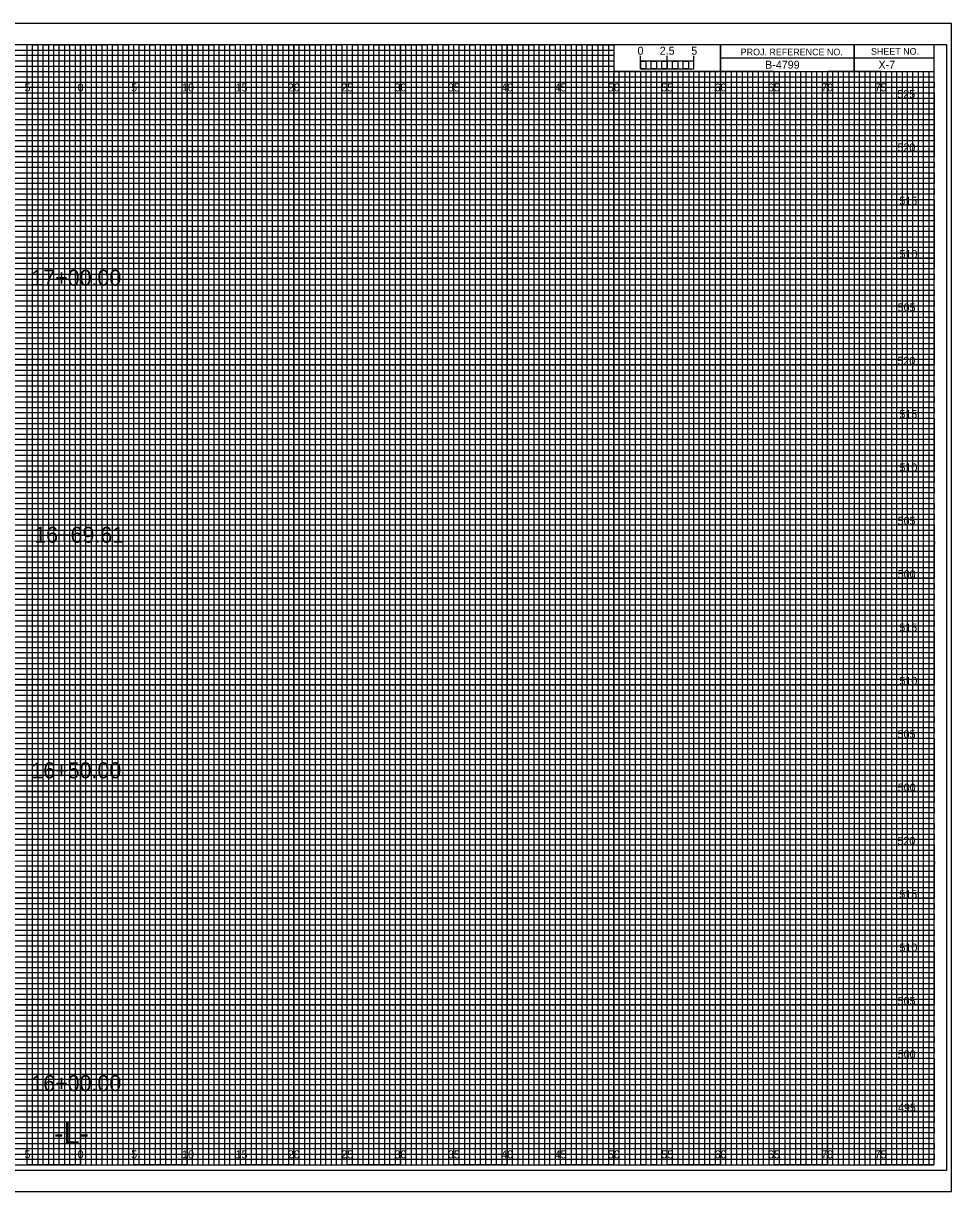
# Model space of a CAD drawing. Extents: x -7 to 162, y 768 to 877.
# Drawn here: x 74.6 to 161.7, y 767.5 to 877 of the extents above; entities that cross this region are included whole.
import ezdxf

# ---------------------------------------------------------------- set-up
doc = ezdxf.new("R2010")
doc.units = 0
for name, color, linetype in [('Prop XS Alignment Label', 7, 'Continuous'), ('Prop XS Bar Scale Labels', 7, 'Continuous'), ('Prop XS Elevation Labels', 7, 'Continuous'), ('Prop XS Offset Labels', 7, 'Continuous'), ('Prop XS Project Number', 7, 'Continuous'), ('Prop XS Sheet Number', 7, 'Continuous'), ('Prop XS Station Labels', 7, 'Continuous'), ('Sheet Cross Section CELL', 7, 'Continuous'), ('Sheet Cross Section Grid Major CELL', 7, 'Continuous'), ('Sheet Cross Section Grid Middle CELL', 7, 'Continuous'), ('Sheet Cross Section Grid Minor 1 CELL', 7, 'Continuous'), ('Sheet Cross Section Grid Minor 2 CELL', 7, 'Continuous'), ('Sheet Cross Section Scale CELL', 7, 'Continuous'), ('Sheet Cutting Line CELL', 7, 'Continuous'), ('Sheet DOT Grid CELL', 7, 'Continuous'), ('Sheet Plot Border Inside CELL', 7, 'Continuous'), ('Sheet Plot Border Outside CELL', 7, 'Continuous')]:
    doc.layers.add(name, color=color, linetype=linetype)

msp = doc.modelspace()

# ---------------------------------------------------------------- linework, layer by layer
at = {"layer": 'Sheet Cross Section CELL'}
for p, q in [((152.5, 875), (152.5, 872.5)), ((152.5, 872.5), (152.5, 875)), ((160, 873.75), (140, 873.75)), ((140, 873.75), (140, 872.5)), ((140, 872.5), (160, 872.5))]:
    msp.add_line(p, q, dxfattribs=at)
for points in [[(160, 875), (0, 875), (0, 770), (160, 770)], [(140, 875), (130, 875), (130, 872.51), (140, 872.51)], [(160, 875), (140, 875), (140, 872.5), (160, 872.5)]]:
    msp.add_lwpolyline(points, close=True, dxfattribs=at)
at = {"layer": 'Sheet Cross Section Grid Major CELL'}
for p, q in [((75, 875), (70, 875)), ((75, 770), (75, 875)), ((85, 875), (80, 875)), ((80, 875), (80, 770)), ((85, 770), (85, 875)), ((95, 875), (90, 875)), ((90, 875), (90, 770)), ((95, 770), (95, 875)), ((105, 875), (100, 875)), ((100, 875), (100, 770)), ((105, 770), (105, 875)), ((115, 875), (110, 875)), ((110, 875), (110, 770)), ((115, 770), (115, 875)), ((125, 875), (120, 875)), ((120, 875), (120, 770)), ((125, 770), (125, 875)), ((130, 875), (130, 770)), ((135, 770), (135, 872.5)), ((145, 872.5), (140, 872.5)), ((140, 872.5), (140, 770)), ((145, 770), (145, 872.5)), ((155, 872.5), (150, 872.5)), ((150, 872.5), (150, 770)), ((155, 770), (155, 872.5)), ((80, 770), (75, 770)), ((90, 770), (85, 770)), ((100, 770), (95, 770)), ((110, 770), (105, 770)), ((120, 770), (115, 770)), ((130, 770), (125, 770)), ((140, 770), (135, 770)), ((150, 770), (145, 770)), ((160, 770), (155, 770)), ((160, 770), (160, 770))]:
    msp.add_line(p, q, dxfattribs=at)
for points in [[(0, 870), (160, 870), (160, 865), (0, 865)], [(0, 860), (160, 860), (160, 855), (0, 855)], [(0, 850), (160, 850), (160, 845), (0, 845)], [(0, 840), (160, 840), (160, 835), (0, 835)], [(0, 830), (160, 830), (160, 825), (0, 825)], [(0, 820), (160, 820), (160, 815), (0, 815)], [(0, 810), (160, 810), (160, 805), (0, 805)], [(0, 800), (160, 800), (160, 795), (0, 795)], [(0, 790), (160, 790), (160, 785), (0, 785)], [(0, 780), (160, 780), (160, 775), (0, 775)]]:
    msp.add_lwpolyline(points, dxfattribs=at)
at = {"layer": 'Sheet Cross Section Grid Middle CELL'}
for points in [[(72.5, 770), (77.5, 770), (77.5, 875), (82.5, 875), (82.5, 770), (87.5, 770), (87.5, 875), (92.5, 875), (92.5, 770), (97.5, 770), (97.5, 875), (102.5, 875), (102.5, 770), (107.5, 770), (107.5, 875), (112.5, 875), (112.5, 770), (117.5, 770), (117.5, 875), (122.5, 875), (122.5, 770), (127.5, 770), (127.5, 875), (129.97, 875), (130, 875), (130, 872.5), (132.5, 872.5), (132.5, 770), (137.5, 770), (137.5, 872.5), (142.5, 872.5), (142.5, 770), (147.5, 770), (147.5, 872.5), (152.5, 872.5), (152.5, 770), (157.5, 770), (157.5, 872.5)], [(0, 872.5), (137.5, 872.5)], [(0, 862.5), (160, 862.5), (160, 867.5), (0, 867.5)], [(0, 852.5), (160, 852.5), (160, 857.5), (0, 857.5)], [(0, 842.5), (160, 842.5), (160, 847.5), (0, 847.5)], [(0, 832.5), (160, 832.5), (160, 837.5), (0, 837.5)], [(0, 822.5), (160, 822.5), (160, 827.5), (0, 827.5)], [(0, 812.5), (160, 812.5), (160, 817.5), (0, 817.5)], [(0, 802.5), (160, 802.5), (160, 807.5), (0, 807.5)], [(0, 792.5), (160, 792.5), (160, 797.5), (0, 797.5)], [(0, 782.5), (160, 782.5), (160, 787.5), (0, 787.5)], [(0, 772.5), (160, 772.5), (160, 777.5), (0, 777.5)]]:
    msp.add_lwpolyline(points, dxfattribs=at)
at = {"layer": 'Sheet Cross Section Grid Minor 1 CELL'}
for p, q in [((0, 874.5), (130, 874.5)), ((130, 873.99), (0, 873.99)), ((130, 874.5), (130, 873.99)), ((0, 873.5), (130, 873.5)), ((130, 872.95), (0, 872.95)), ((130, 873.5), (130, 872.95)), ((0, 872), (160, 872))]:
    msp.add_line(p, q, dxfattribs=at)
for points in [[(0, 871.5), (135, 871.5), (160, 871.5), (160, 871), (0, 871)], [(0, 870.5), (160, 870.5), (160, 869.5), (0, 869.5)], [(0, 869), (160, 869), (160, 868.5), (0, 868.49)], [(0, 868), (160, 868), (160, 867), (0, 867)], [(0, 866.5), (160, 866.5), (160, 866), (0, 866)], [(0, 865.5), (160, 865.5), (160, 864.5), (0, 864.5)], [(0, 864), (160, 864), (160, 863.5), (0, 863.5)], [(0, 863), (160, 863), (160, 862), (0, 862)], [(0, 861.5), (160, 861.5), (160, 861), (0, 861)], [(0, 860.5), (160, 860.5), (160, 859.5), (0, 859.5)], [(0, 859), (160, 859), (160, 858.5), (0, 858.5)], [(0, 858), (160, 858), (160, 856.98), (160, 856.5), (160, 856), (0, 856)], [(0, 857), (160, 857), (160, 856.5), (0, 856.5)], [(0, 855.5), (160, 855.5), (160, 854.5), (0, 854.51)], [(0, 854.51), (160, 854.5), (160, 854), (0, 854)], [(0, 853.5), (160, 853.5), (160, 853), (0, 853)], [(0, 852), (160, 852), (160, 851.5), (0, 851.5)], [(0, 851), (160, 851), (160, 850.5), (0, 850.5)], [(-0.04, 849.45), (160, 849.45), (160, 848.94), (-0.04, 848.94)], [(0, 848.5), (160, 848.5), (160, 848), (0, 848)], [(0, 847), (160, 847), (160, 846.5), (0, 846.5)], [(0, 846), (160, 846), (160, 845.5), (0, 845.5)], [(0, 844.5), (160, 844.5), (160, 844), (0, 844)], [(0, 843.5), (160, 843.5), (160, 843), (0, 843)], [(0, 842), (160, 842), (160, 841.5), (0, 841.5)], [(0, 841), (160, 841), (160, 840.5), (0, 840.5)], [(0, 839.5), (160, 839.5), (160, 838.99), (0, 839)], [(0, 838.5), (160, 838.5), (160, 838), (0, 838)], [(0, 837), (160, 837), (160, 836.5), (0, 836.5)], [(0, 836), (160, 836), (160, 835.5), (0, 835.5)], [(0, 834.5), (160, 834.5), (160, 834), (0, 834)], [(0, 833.5), (160, 833.5), (160, 833), (0, 833)], [(0, 832), (160, 832), (160, 831.5), (0, 831.5)], [(0, 831), (160, 831), (160, 830.5), (0, 830.5)], [(0, 829.5), (160, 829.5), (160, 829), (0, 829)], [(0, 828.5), (160.03, 828.46), (160, 828), (0, 828)], [(0, 827), (160, 827), (160, 826.5), (0, 826.5)], [(0, 826), (160, 826), (160, 825.5), (0, 825.5)], [(0, 824.5), (160, 824.5), (160, 824), (0, 824)], [(0, 823.5), (160, 823.5), (160, 823), (0, 823)], [(0, 822), (160, 822), (160, 821.5), (0, 821.5)], [(0, 821), (160, 821), (160, 820.5), (0, 820.5)], [(0, 819.5), (160, 819.5), (160, 819), (0, 819)], [(0, 818.5), (160, 818.5), (160, 818), (0, 818)], [(0, 817), (160, 817), (160, 816.5), (0, 816.5)], [(0, 816), (160, 816), (160, 815.5), (0, 815.5)], [(0, 814.5), (160, 814.5), (160, 814), (0, 814)], [(0, 813.5), (160, 813.5), (160, 813), (0, 813)], [(0, 812), (160, 812), (160, 811.5), (0, 811.5)], [(0, 811), (160, 811), (160, 810.5), (0, 810.5)], [(0, 809.5), (160, 809.5), (160, 808.99), (0, 809)], [(0, 808.5), (160, 808.5), (160, 808), (0, 808)], [(0, 807), (160, 807), (160, 806.5), (0, 806.5)], [(0, 806), (160, 806), (160, 805.5), (0, 805.5)], [(0, 804.5), (160, 804.5), (160, 804), (0, 804)], [(0, 803.5), (160, 803.5), (160, 803), (0, 803)], [(0, 802), (160, 802), (160, 801.5), (0, 801.5)], [(0, 801), (160, 801), (160, 800.5), (0, 800.5)], [(0, 799.5), (160, 799.5), (160, 799), (0, 799)], [(0, 798.5), (160.03, 798.46), (160, 798), (0, 798)], [(0, 797), (160, 797), (160, 796.5), (0, 796.5)], [(0, 796), (160, 796), (160, 795.5), (0, 795.5)], [(0, 794.5), (160, 794.5), (160, 794), (0, 794)], [(0, 793.5), (160, 793.5), (160, 793), (0, 793)], [(0, 792), (160, 792), (160, 791.5), (0, 791.5)], [(0, 791), (160, 791), (160, 790.5), (0, 790.5)], [(0, 789.5), (160, 789.5), (160, 789), (0, 789)], [(0, 788.5), (160, 788.5), (160, 788), (0, 788)], [(0, 787), (160, 787), (160, 786.5), (0, 786.5)], [(0, 786), (160, 786), (160, 785.5), (0, 785.5)], [(0, 784.5), (160, 784.5), (160, 784), (0, 784)], [(0, 783.5), (160, 783.5), (160, 783), (0, 783)], [(0, 782), (160, 782), (160, 781.5), (0, 781.5)], [(0, 781), (160, 781), (160, 780.5), (0, 780.5)], [(0, 779.5), (160, 779.5), (160, 779), (0, 779)], [(0, 778.5), (160, 778.5), (160, 778), (0, 778)], [(0, 777), (160, 777), (160, 776.5), (0, 776.5)], [(0, 776), (160, 776), (160, 775.5), (0, 775.5)], [(0, 774.5), (160, 774.5), (160, 774), (0, 774)], [(0, 773.5), (160, 773.5), (160, 773), (0, 773)], [(0, 772), (160, 772), (160, 771.5), (0, 771.5)], [(0, 771), (160, 771), (160, 770.5), (0, 770.5)]]:
    msp.add_lwpolyline(points, dxfattribs=at)
at = {"layer": 'Sheet Cross Section Grid Minor 2 CELL'}
for p, q in [((133.5, 872.5), (133, 872.5)), ((133, 872.5), (133, 770)), ((133.5, 770), (133.5, 872.5)), ((134.5, 872.5), (134, 872.5)), ((134, 872.5), (134, 770)), ((134.5, 770), (134.5, 872.5)), ((133, 770), (132.5, 770)), ((134, 770), (133.5, 770))]:
    msp.add_line(p, q, dxfattribs=at)
for points in [[(75, 770), (75.5, 770), (75.5, 875), (76, 875), (76, 770)], [(76, 770), (76.5, 770), (76.5, 875), (77, 875), (77, 770)], [(77.5, 770), (78, 770), (78, 875), (78.5, 875), (78.5, 770)], [(78.5, 770), (79, 770), (79, 875), (79.5, 875), (79.5, 770)], [(80, 770), (80.5, 770), (80.5, 875), (81, 875), (81, 770)], [(81, 770), (81.5, 770), (81.5, 875), (82, 875), (82, 770)], [(82.5, 770), (83, 770), (83, 875), (83.5, 875), (83.5, 770)], [(83.5, 770), (84, 770), (84, 875), (84.5, 875), (84.5, 770)], [(85, 770), (85.5, 770), (85.5, 875), (86, 875), (86, 770)], [(86, 770), (86.5, 770), (86.5, 875), (87, 875), (87, 770)], [(87.5, 770), (88, 770), (88, 875), (88.5, 875), (88.5, 770)], [(88.5, 770), (89, 770), (89, 875), (89.5, 875), (89.5, 770)], [(90, 770), (90.5, 770), (90.5, 875), (91, 875), (91, 770)], [(91, 770), (91.5, 770), (91.5, 875), (92, 875), (92, 770)], [(92.5, 770), (93, 770), (93, 875), (93.5, 875), (93.5, 770)], [(93.5, 770), (94, 770), (94, 875), (94.5, 875), (94.5, 770)], [(95, 770), (95.5, 770), (95.5, 875), (96, 875), (96, 770)], [(96, 770), (96.5, 770), (96.5, 875), (97, 875), (97, 770)], [(97.5, 770), (98, 770), (98, 875), (98.5, 875), (98.5, 770)], [(98.5, 770), (99, 770), (99, 875), (99.5, 875), (99.5, 770)], [(100, 770), (100.5, 770), (100.5, 875), (101, 875), (101, 770)], [(101, 770), (101.5, 770), (101.5, 875), (102, 875), (102, 770)], [(102.5, 770), (103, 770), (103, 875), (103.5, 875), (103.5, 770)], [(103.5, 770), (104, 770), (104, 875), (104.5, 875), (104.5, 770)], [(105, 770), (105.5, 770), (105.5, 875), (106, 875), (106, 770)], [(106, 770), (106.5, 770), (106.5, 875), (107, 875), (107, 770)], [(107.5, 770), (108, 770), (108, 875), (108.5, 875), (108.5, 770)], [(108.5, 770), (109, 770), (109, 875), (109.5, 875), (109.5, 770)], [(110, 770), (110.5, 770), (110.5, 875), (111, 875), (111, 770)], [(111, 770), (111.5, 770), (111.5, 875), (112, 875), (112, 770)], [(112.5, 770), (113, 770), (113, 875), (113.5, 875), (113.5, 770)], [(113.5, 770), (114, 770), (114, 875), (114.5, 875), (114.5, 770)], [(115, 770), (115.5, 770), (115.5, 875), (116, 875), (116, 770)], [(116, 770), (116.5, 770), (116.5, 875), (117, 875), (117, 770)], [(117.5, 770), (118, 770), (118, 875), (118.5, 875), (118.5, 770)], [(118.5, 770), (119, 770), (119, 875), (119.5, 875), (119.5, 770)], [(120, 770), (120.5, 770), (120.5, 875), (121, 875), (121, 770)], [(121, 770), (121.5, 770), (121.5, 875), (122, 875), (122, 770)], [(122.5, 770), (123, 770), (123, 875), (123.5, 875), (123.5, 770)], [(123.5, 770), (124, 770), (124, 875), (124.5, 875), (124.5, 770)], [(125, 770), (125.5, 770), (125.5, 875), (126, 875), (126, 770)], [(126, 770), (126.5, 770), (126.5, 875), (127, 875), (127, 770)], [(127.5, 770), (128, 770), (128, 875), (128.5, 875), (128.5, 770)], [(128.5, 770), (129, 770), (129, 875), (129.5, 875), (129.5, 770)], [(130, 770), (130.5, 770), (130.5, 872.5), (131.01, 872.5), (131.01, 770)], [(131, 770), (131.5, 770), (131.5, 872.5), (132, 872.5), (132, 770)], [(135, 770), (135.49, 770), (135.49, 872.5), (136, 872.5), (136, 770)], [(136, 770), (136.5, 770), (136.5, 872.5), (137.03, 872.5), (137.03, 770)], [(137.5, 770), (138, 770), (138, 872.5), (138.5, 872.5), (138.5, 770)], [(138.5, 770), (139, 770), (139, 872.5), (139.5, 872.5), (139.5, 770)], [(140, 770), (140.5, 770), (140.5, 872.5), (141, 872.5), (141, 770)], [(141, 770), (141.5, 770), (141.5, 872.5), (142, 872.5), (142, 770)], [(142.5, 770), (143, 770), (143, 872.5), (143.5, 872.5), (143.5, 770)], [(143.5, 770), (144, 770), (144, 872.5), (144.5, 872.5), (144.5, 770)], [(145, 770), (145.5, 770), (145.5, 872.5), (146, 872.5), (146, 770)], [(146, 770), (146.5, 770), (146.5, 872.5), (147, 872.5), (147, 770)], [(147.5, 770), (148, 770), (148, 872.5), (148.5, 872.5), (148.5, 770)], [(148.5, 770), (149, 770), (149, 872.5), (149.5, 872.5), (149.5, 770)], [(150, 770), (150.5, 770), (150.5, 872.5), (151, 872.5), (151, 770)], [(151, 770), (151.5, 770), (151.5, 872.5), (152, 872.5), (152, 770)], [(152.5, 770), (153, 770), (153, 872.5), (153.5, 872.5), (153.5, 770)], [(153.5, 770), (154, 770), (154, 872.5), (154.5, 872.5), (154.5, 770)], [(155, 770), (155.5, 770), (155.5, 872.5), (156, 872.5), (156, 770)], [(156, 770), (156.5, 770), (156.5, 872.5), (157, 872.5), (157, 770)], [(157.5, 770), (158, 770), (158, 872.5), (158.5, 872.5), (158.5, 770)], [(158.5, 770), (159, 770), (159, 872.5), (159.5, 872.5), (159.5, 770)]]:
    msp.add_lwpolyline(points, dxfattribs=at)
at = {"layer": 'Sheet Cross Section Scale CELL'}
for p, q in [((132.5, 872.75), (132.5, 873.95)), ((132.5, 873.45), (132.5, 873.95)), ((135, 872.75), (135, 873.95)), ((137.5, 872.75), (137.5, 873.95)), ((137.5, 873.45), (137.5, 873.95))]:
    msp.add_line(p, q, dxfattribs=at)
for points in [[(137.5, 873.45), (132.5, 873.45), (132.5, 872.75), (137.5, 872.75)], [(132.5, 873.45), (133, 873.45), (133, 872.75), (132.5, 872.75)], [(133.5, 873.45), (134, 873.45), (134, 872.75), (133.5, 872.75)], [(134.5, 873.45), (135, 873.45), (135, 872.75), (134.5, 872.75)], [(135.5, 873.45), (136, 873.45), (136, 872.75), (135.5, 872.75)], [(136.5, 873.45), (137, 873.45), (137, 872.75), (136.5, 872.75)]]:
    msp.add_lwpolyline(points, close=True, dxfattribs=at)
at = {"layer": 'Sheet Cutting Line CELL'}
for p, q in [((161.65, 877), (-6.7, 877)), ((-6.7, 767.5), (161.65, 767.5))]:
    msp.add_line(p, q, dxfattribs=at)
at = {"layer": 'Sheet DOT Grid CELL'}
for p, q in [((75, 770), (75, 875)), ((80, 770), (80, 875)), ((85, 770), (85, 875)), ((90, 770), (90, 875)), ((95, 770), (95, 875)), ((100, 770), (100, 875)), ((105, 770), (105, 875)), ((110, 770), (110, 875)), ((115, 770), (115, 875)), ((120, 770), (120, 875)), ((125, 770), (125, 875)), ((130, 770), (130, 872.34)), ((135, 770), (135, 872.34)), ((140, 770), (140, 872.34)), ((145, 770), (145, 872.34)), ((150, 770), (150, 872.34)), ((155, 770), (155, 872.34)), ((0, 870), (160, 870)), ((0, 865), (160, 865)), ((0, 860), (160, 860)), ((0, 855), (160, 855)), ((0, 850), (160, 850)), ((0, 845), (160, 845)), ((0, 840), (160, 840)), ((0, 835), (160, 835)), ((0, 830), (160, 830)), ((0, 825), (160, 825)), ((0, 820), (160, 820)), ((0, 815), (160, 815)), ((0, 810), (160, 810)), ((0, 805), (160, 805)), ((0, 800), (160, 800)), ((0, 795), (160, 795)), ((0, 790), (160, 790)), ((0, 785), (160, 785)), ((0, 780), (160, 780)), ((0, 775), (160, 775))]:
    msp.add_line(p, q, dxfattribs=at)
at = {"layer": 'Sheet Plot Border Inside CELL'}
msp.add_lwpolyline([(-5.4, 769.5), (161.2, 769.5), (161.2, 875), (-5.4, 875)], close=True, dxfattribs=at)
at = {"layer": 'Sheet Plot Border Outside CELL'}
msp.add_lwpolyline([(-6.7, 767.5), (161.65, 767.5), (161.65, 877), (-6.7, 877)], close=True, dxfattribs=at)

# ---------------------------------------------------------------- texts
at = {"layer": 'Prop XS Alignment Label'}
msp.add_text('-L-', height=2, dxfattribs=at).set_placement((77.53, 772))
at = {"layer": 'Prop XS Bar Scale Labels'}
for s, p in [('2.5', (134.29, 874.06)), ('5', (137.24, 874.06))]:
    msp.add_text(s, height=0.75, dxfattribs=at).set_placement(p)
at = {"layer": 'Prop XS Elevation Labels'}
for s, p in [('525', (156.56, 870)), ('520', (156.57, 865)), ('515', (156.75, 860)), ('510', (156.76, 855)), ('505', (156.59, 850)), ('520', (156.57, 845)), ('515', (156.75, 840)), ('510', (156.76, 835)), ('505', (156.59, 830)), ('500', (156.6, 825)), ('515', (156.75, 820)), ('510', (156.76, 815)), ('505', (156.59, 810)), ('500', (156.6, 805)), ('520', (156.57, 800)), ('515', (156.75, 795)), ('510', (156.76, 790)), ('505', (156.59, 785)), ('500', (156.6, 780)), ('495', (156.62, 775))]:
    msp.add_text(s, height=0.75, dxfattribs=at).set_placement(p)
at = {"layer": 'Prop XS Offset Labels'}
for s, p in [('5', (74.74, 870.62)), ('0', (79.73, 870.62)), ('0', (79.73, 870.62)), ('5', (84.74, 870.62)), ('10', (89.52, 870.62)), ('15', (94.53, 870.62)), ('20', (99.43, 870.62)), ('25', (104.44, 870.62)), ('30', (109.43, 870.62)), ('35', (114.44, 870.62)), ('40', (119.43, 870.62)), ('45', (124.44, 870.62)), ('50', (129.43, 870.62)), ('55', (134.44, 870.62)), ('60', (139.43, 870.62)), ('65', (144.44, 870.62)), ('70', (149.43, 870.62)), ('75', (154.44, 870.62)), ('5', (74.74, 770.62)), ('0', (79.73, 770.62)), ('0', (79.73, 770.62)), ('5', (84.74, 770.62)), ('10', (89.52, 770.62)), ('15', (94.53, 770.62)), ('20', (99.43, 770.62)), ('25', (104.44, 770.62)), ('30', (109.43, 770.62)), ('35', (114.44, 770.62)), ('40', (119.43, 770.62)), ('45', (124.44, 770.62)), ('50', (129.43, 770.62)), ('55', (134.44, 770.62)), ('60', (139.43, 770.62)), ('65', (144.44, 770.62)), ('70', (149.43, 770.62)), ('75', (154.44, 770.62))]:
    msp.add_text(s, height=0.75, dxfattribs=at).set_placement(p)
at = {"layer": 'Prop XS Project Number'}
msp.add_text('B-4799', height=0.75, dxfattribs=at).set_placement((144.17, 872.75))
at = {"layer": 'Prop XS Sheet Number'}
msp.add_text('X-7', height=0.75, dxfattribs=at).set_placement((154.79, 872.75))
at = {"layer": 'Prop XS Station Labels'}
for s, p in [('17+00.00', (75.39, 852.41)), ('16+69.61', (75.66, 828.32)), ('16+50.00', (75.39, 806.24)), ('16+00.00', (75.39, 776.92))]:
    msp.add_text(s, height=1.5, dxfattribs=at).set_placement(p)
at = {"layer": 'Sheet Cross Section CELL'}
for s, p in [('PROJ. REFERENCE NO.', (141.88, 874)), ('SHEET NO.', (154.09, 874.06))]:
    msp.add_text(s, height=0.625, dxfattribs=at).set_placement(p)
at = {"layer": 'Sheet Cross Section Scale CELL'}
msp.add_text('0', height=0.75, dxfattribs=at).set_placement((132.21, 874.06))

doc.saveas('drawing.dxf')
